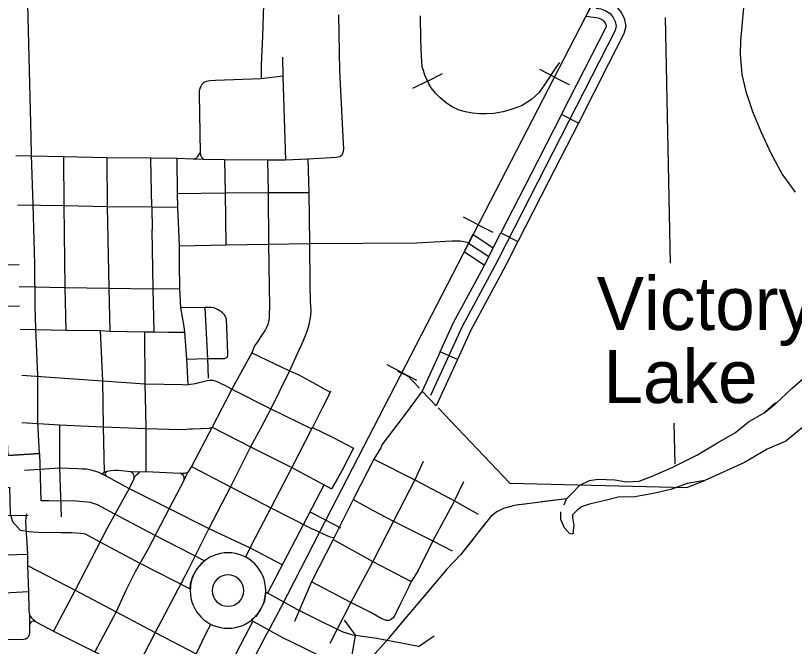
# Model space of a CAD drawing. Extents: x 1164457 to 1439835, y 1590918 to 1773502.
# Drawn here: x 1298324 to 1304504, y 1633633 to 1638642 of the extents above; entities that cross this region are included whole.
import ezdxf

# ---------------------------------------------------------------- set-up
doc = ezdxf.new("R2010")
doc.units = 0
for name, color, linetype in [('Level 15', 7, 'Continuous'), ('Level 24', 7, 'Continuous'), ('Level 31', 7, 'Continuous'), ('Level 33', 7, 'Continuous'), ('Level 34', 7, 'Continuous'), ('Level 35', 7, 'Continuous'), ('Level 37', 7, 'Continuous'), ('Level 40', 7, 'Continuous'), ('Level 43', 7, 'Continuous'), ('Level 5', 7, 'Continuous'), ('Level 6', 7, 'Continuous')]:
    doc.layers.add(name, color=color, linetype=linetype)

msp = doc.modelspace()

# ---------------------------------------------------------------- linework, layer by layer
at = {"layer": 'Level 15'}
for points in [[(1298513.3, 1635164.1), (1298499.6, 1635413.1), (1298499.8, 1635787.6), (1298484.8, 1636155.1), (1298480.5, 1636337.1), (1298476.5, 1636667.6), (1298463.9, 1637142.9), (1298451.5, 1637530.8), (1298447.9, 1637680.7), (1298415.1, 1638944.2), (1298391.3, 1639807.5), (1298141.4, 1639800.3)], [(1298141.4, 1639800.3), (1298165.2, 1638937.6), (1298197.9, 1637674.4), (1298201.6, 1637523.8), (1298214, 1637135.6), (1298226.5, 1636662.8), (1298230.6, 1636332.7), (1298234.9, 1636147.1), (1298249.8, 1635782.5), (1298249.6, 1635406.4), (1298263.8, 1635147.9), (1298513.3, 1635164.1)], [(1299709.5, 1634089.1), (1299713.1, 1634128.9), (1299731.6, 1634191.5), (1299764.3, 1634252.6), (1299823.2, 1634311.7), (1299430.5, 1634513.2), (1299110.4, 1634682.9), (1298975, 1634756), (1298917.6, 1634774.7), (1298863.9, 1634781.5), (1298775.7, 1634787.8), (1298686.6, 1634787.1), (1298587.9, 1634789.5), (1298548.2, 1634788.5), (1298528.1, 1634789.4), (1298516.2, 1635164.2), (1298056.3, 1635134.5), (1297302.4, 1635106.3), (1297059.9, 1635097.3), (1296805.9, 1635087.8), (1296448.4, 1635077.9), (1295766.2, 1635051.5), (1295337.8, 1635042.2)], [(1295337.8, 1635042.2), (1295343.3, 1634792.2), (1295773.7, 1634801.6), (1296456.7, 1634828), (1296814, 1634837.9), (1297069.3, 1634847.5), (1297311.7, 1634856.5), (1298069.1, 1634884.8), (1298274.5, 1634898.1), (1298281.3, 1634685.8), (1298300.3, 1634623.8), (1298360.7, 1634555.9), (1298432.6, 1634544.9), (1298463.5, 1634541.9), (1298546, 1634538.3), (1298588.1, 1634539.5), (1298684.6, 1634537.1), (1298767.8, 1634537.8), (1298839.2, 1634532.6), (1298862.6, 1634529.7), (1298876.1, 1634525.3), (1298992.5, 1634462.4), (1299314.9, 1634291.5), (1299709.5, 1634089.1)], [(1301022.5, 1633718.7), (1301000.5, 1633722.5), (1300977.5, 1633729.2), (1300924.1, 1633746.6), (1300872.6, 1633770.1), (1300722.2, 1633844.5), (1300558.7, 1633924.9), (1300308.9, 1634062.9), (1300305.7, 1634033.7), (1300298.5, 1633992.4), (1300268.7, 1633925.6), (1300230.3, 1633870.2), (1300194.6, 1633840.5)], [(1300194.6, 1633840.5), (1300443.1, 1633703.2), (1300611.5, 1633620.3), (1300765.2, 1633544.2), (1300833.2, 1633513.3), (1300904.1, 1633490.2), (1300944, 1633478.6), (1300979.3, 1633472.4), (1301022.5, 1633718.7)], [(1301522.1, 1633632.6), (1301191.7, 1633694.5), (1301022.5, 1633718.7)]]:
    msp.add_lwpolyline(points, dxfattribs=at)
at = {"layer": 'Level 24'}
for radius, start, end in [(300, 90, 270), (300, 270, 90), (125, 90, 270), (125, 270, 90)]:
    msp.add_arc((1300009.2, 1634076.3), radius, start, end, dxfattribs=at)
at = {"layer": 'Level 31'}
for p, q in [((1302789.7, 1637787.6), (1302656.1, 1637855.9)), ((1302175.4, 1636915.6), (1302308.9, 1636847.4)), ((1301830.1, 1635910.3), (1301693.7, 1635972.6))]:
    msp.add_line(p, q, dxfattribs=at)
for points in [[(1302848.5, 1638633.1), (1302922.4, 1638775.5), (1302987.8, 1638767.8), (1303043.1, 1638745.2), (1303092.8, 1638713.8), (1303128.4, 1638666.8), (1303152.1, 1638621.5), (1303167, 1638557), (1303151.7, 1638495.6), (1303030, 1638257.7)], [(1302930.9, 1638699), (1302968.9, 1638694.5), (1303008.7, 1638678.3), (1303041.2, 1638657.7), (1303064.9, 1638626.5), (1303081.2, 1638595.3), (1303089.9, 1638557.7), (1303081, 1638522.1), (1302154.7, 1636710.5), (1302103.5, 1636609.2), (1301867.2, 1636172.2), (1301617.5, 1635624.9)], [(1302896.5, 1638326), (1303010.3, 1638548.6), (1303012.8, 1638558.4), (1303010.3, 1638569), (1303001.4, 1638586.2), (1302989.7, 1638601.6), (1302974.2, 1638611.3), (1302950, 1638621.2), (1302848.5, 1638633.1)], [(1302656.1, 1637855.9), (1302896.5, 1638326)], [(1303030, 1638257.7), (1302789.7, 1637787.6)], [(1302656.1, 1637855.9), (1302415.7, 1637385.8)], [(1302789.7, 1637787.6), (1302549.3, 1637317.5)], [(1302415.7, 1637385.8), (1302175.4, 1636915.6)], [(1302549.3, 1637317.5), (1302308.9, 1636847.4)], [(1301953.4, 1636902.1), (1301884.1, 1636768), (1302045.6, 1636660)], [(1301931.7, 1636449.2), (1302037, 1636644), (1302087.9, 1636744.5), (1302175.4, 1636915.6)], [(1302045.6, 1636660), (1302113.7, 1636795), (1301953.4, 1636902.1)], [(1301918.7, 1636835), (1302079.4, 1636727.7)], [(1302308.9, 1636847.4), (1302221.6, 1636676.5), (1302169.9, 1636574.5), (1302063.6, 1636377.9)], [(1301693.7, 1635972.6), (1301800, 1636205.6), (1301931.7, 1636449.2)], [(1302063.6, 1636377.9), (1301934.3, 1636138.7), (1301830.1, 1635910.3)], [(1301693.7, 1635972.6), (1301551.1, 1635660)], [(1301830.1, 1635910.3), (1301662.4, 1635542.6), (1301551.1, 1635660)]]:
    msp.add_lwpolyline(points, dxfattribs=at)
at = {"layer": 'Level 33'}
for points in [[(1300290.7, 1638725.5), (1300282.5, 1638477.5), (1300273.1, 1638250), (1300273.9, 1638139.8)], [(1300887.2, 1638647.2), (1300895.4, 1638203.5), (1300918.2, 1637732.5), (1300923.9, 1637628.1), (1300926.3, 1637587.3), (1300923.9, 1637561.2), (1300915.7, 1637535.1), (1300909.2, 1637530.2), (1300897, 1637521.2), (1300882.5, 1637516.8), (1300867.6, 1637514.7), (1300824.4, 1637512.2), (1300644.2, 1637502.5), (1300465.2, 1637494.2), (1300324.2, 1637492.6), (1299982.8, 1637495.6), (1299819, 1637497.5), (1299734.2, 1637500.8), (1299603.8, 1637506.5), (1299397, 1637508.8), (1299049.1, 1637513.1), (1298704.4, 1637519.7), (1298326.6, 1637527.3)], [(1300442.3, 1638311.9), (1300445.6, 1638160.2), (1300465.2, 1637494.2)], [(1300445.6, 1638160.2), (1300273.9, 1638139.8), (1299909.5, 1638126.8), (1299867.9, 1638124.3), (1299836.9, 1638118.6), (1299816.5, 1638108.8), (1299801.8, 1638095), (1299793.7, 1638079.5), (1299787.2, 1638064), (1299781.5, 1638040.3), (1299781.5, 1638019.6), (1299789.7, 1637550.5)], [(1298704.4, 1637519.7), (1298708, 1637132.5), (1298715.4, 1636483.7), (1298722.8, 1636142.5)], [(1300644.2, 1637502.5), (1300651.9, 1637237.2), (1300656.9, 1636831.6), (1300659.3, 1636497.8), (1300662.3, 1636374.9), (1300666.1, 1636297.5), (1300665.4, 1636256.7), (1300649.9, 1636187.8), (1300650.4, 1636185.1), (1300637.5, 1636140.1), (1300615.3, 1636084.3), (1300595.8, 1636034.6), (1300572.9, 1635985.2), (1300498.3, 1635821.5), (1300348.1, 1635520.2), (1300268.2, 1635362.8), (1300188.1, 1635218.5), (1300029.6, 1634898.8), (1299858.6, 1634569.1), (1299690, 1634234.4), (1299432.1, 1633742.5), (1299268.3, 1633425.5)], [(1299404.1, 1637122), (1299401, 1637369), (1299397, 1637508.8)], [(1299603.8, 1637506.5), (1299606.3, 1637228), (1299607.9, 1637120.2), (1299621.5, 1636814.4), (1299622.7, 1636672.6), (1299624.3, 1636473.8), (1299631.8, 1636321.1), (1299660.3, 1636172.6), (1299663.6, 1636128.5), (1299680.9, 1635914.6), (1299691, 1635712.9)], [(1299734.2, 1637500.8), (1299756.3, 1637510.6), (1299770.9, 1637523.6), (1299789.7, 1637550.5), (1299791.3, 1637534.2), (1299800.3, 1637517.1), (1299819, 1637497.5)], [(1300324.2, 1637492.6), (1300327.4, 1637235.7), (1300331.1, 1636827.2), (1300337.6, 1636325), (1300337.2, 1636269.8), (1300335.7, 1636238.6), (1300330.9, 1636212.2), (1300325, 1636189.8), (1300311.4, 1636159.1), (1300303.2, 1636143.6), (1300264.9, 1636084.5), (1300242.5, 1636050.3), (1300221, 1636019.1), (1300198.7, 1635965), (1300039, 1635675.2), (1299884, 1635373.2), (1299718.8, 1635060.5), (1299691.4, 1635015.4), (1299667.2, 1634968), (1299658.7, 1634950.7), (1299543.2, 1634727.2), (1299372.7, 1634402.4), (1299273.8, 1634223.8), (1299196.9, 1634071.4), (1299121.5, 1633908.3), (1298952.3, 1633588.7)], [(1299982.8, 1637495.6), (1299987.9, 1637235.1), (1299992.3, 1636821.3)], [(1299606.3, 1637228), (1299987.9, 1637235.1)], [(1298338.9, 1637139.3), (1298708, 1637132.5), (1299051.9, 1637126.3), (1299404.1, 1637122), (1299607.9, 1637120.2)], [(1299051.9, 1637126.3), (1299063.9, 1636477.5), (1299072.2, 1636136.3)], [(1299424.7, 1636129.2), (1299415.6, 1636472.6), (1299408.5, 1636940.1)], [(1299621.5, 1636814.4), (1299992.3, 1636821.3), (1300331.1, 1636827.2), (1300656.9, 1636831.6), (1301505.6, 1636837.6), (1301786, 1636852.1), (1301851.1, 1636852.1), (1301868, 1636849.9), (1301921.2, 1636839.8)], [(1297988.3, 1636653.2), (1298351.5, 1636665.2)], [(1298352.2, 1636491.1), (1298715.4, 1636483.7), (1299063.9, 1636477.5), (1299415.6, 1636472.6), (1299624.3, 1636473.8)], [(1298355.5, 1636334.9), (1297988.5, 1636324.6), (1297695.9, 1636307.2), (1297369.9, 1636294.6), (1297084.8, 1636288.8), (1297071.6, 1636285.5), (1297057.4, 1636279), (1297047.3, 1636269.3), (1297042.8, 1636260.1), (1297039, 1636239.5), (1297039, 1636226), (1297039.9, 1636163.3), (1297055.2, 1635732.6), (1297058.4, 1635340.9), (1297064.6, 1634972.4)], [(1298359.8, 1636151.1), (1298722.8, 1636142.5), (1298994, 1636140), (1299072.2, 1636136.3), (1299346.8, 1636129.2), (1299424.7, 1636129.2), (1299536.2, 1636128.5), (1299663.6, 1636128.5)], [(1298994, 1636140), (1299012.8, 1635740.7), (1299018.3, 1635375.9), (1299026.4, 1635016.7)], [(1299346.8, 1636129.2), (1299349.8, 1635717.2), (1299354.1, 1635496.9), (1299358.4, 1635361.7), (1299358.6, 1635021.2)], [(1300198.7, 1635965), (1300498.3, 1635821.5), (1300523.3, 1635811.5), (1300571.9, 1635789.3), (1300659.2, 1635741.4), (1300820.8, 1635652.4)], [(1298374.8, 1635785.1), (1299012.8, 1635740.7), (1299349.8, 1635717.2), (1299649.7, 1635711), (1299668.8, 1635710), (1299691, 1635712.9), (1299711.7, 1635715.7), (1299751, 1635720), (1299781.8, 1635727.2), (1299832.7, 1635741.9), (1299846.3, 1635745.2), (1299859, 1635747.2), (1299885.5, 1635747.2), (1299906.2, 1635741.5), (1299928.1, 1635732.4), (1299958.7, 1635718.8), (1299983.9, 1635708.1), (1300039, 1635675.2), (1300348.1, 1635520.2), (1300673.9, 1635360.6)], [(1300823.8, 1635658.8), (1300796.9, 1635602.4), (1300756.9, 1635523.7), (1300682.3, 1635376.1), (1300676.9, 1635367), (1300518, 1635058.5), (1300352.3, 1634739.2), (1300261.8, 1634567.5), (1300188.9, 1634422.2), (1300147.5, 1634342.6)], [(1301551.1, 1635660), (1301398.7, 1635454.4), (1301229.9, 1635233.2), (1301221, 1635209.7), (1301166.2, 1635120.7), (1301001.5, 1634798.3), (1300851, 1634496.7), (1300843.2, 1634481), (1300671.1, 1634145.3), (1300536.1, 1633830.2)], [(1298374.6, 1635409.8), (1298672.4, 1635392.1), (1299018.3, 1635375.9), (1299358.4, 1635361.7), (1299633.7, 1635356.1), (1299679.7, 1635357.3), (1299705.8, 1635359), (1299728.8, 1635359.6), (1299861, 1635365.9), (1299884, 1635373.2)], [(1298672.4, 1635392.1), (1298671.7, 1635049.5), (1298685.6, 1634662.1)], [(1299884, 1635373.2), (1300188.1, 1635218.5), (1300515, 1635052.1), (1300830.1, 1634884.7)], [(1300679.2, 1635369.7), (1300843.7, 1635290.4), (1301005.5, 1635206.2)], [(1301166.2, 1635120.7), (1301492.3, 1634955.6)], [(1298395.3, 1635031.2), (1298671.7, 1635049.5), (1298818.2, 1635046.5), (1298851.3, 1635043.4), (1298888.1, 1635042.4), (1298911.3, 1635038), (1298951.3, 1635026.5), (1298981.8, 1635015.1), (1299007.4, 1635004.2), (1299044.6, 1634983.6), (1299225.2, 1634887.2), (1299543.2, 1634727.2), (1299858.6, 1634569.1), (1300185.8, 1634415.9), (1300440.7, 1634281.6)], [(1299007.4, 1635004.2), (1299026.4, 1635016.7), (1299037.7, 1635021.7), (1299049.7, 1635024.9), (1299080.5, 1635029.6), (1299111.2, 1635030.9), (1299139.2, 1635031.3), (1299239.3, 1635022.8), (1299310.8, 1635019), (1299358.6, 1635021.2), (1299629.8, 1635007.3), (1299663.3, 1635007.7), (1299676, 1635010), (1299691, 1635016.1)], [(1299718.8, 1635060.5), (1300029.6, 1634898.8), (1300349.3, 1634732.8), (1300666.3, 1634570.4), (1300816.7, 1634503.9), (1300851, 1634496.7)], [(1299044.6, 1634983.6), (1299037.3, 1634995.1), (1299036.5, 1634999.7), (1299037.3, 1635009.4), (1299040.4, 1635015.1), (1299049.7, 1635024.9)], [(1299239.3, 1635022.8), (1299247, 1635015.9), (1299254.7, 1635006.7), (1299259.3, 1634995.1), (1299263.1, 1634983.6), (1299261.7, 1634965.2), (1299271.6, 1634983.6), (1299285.4, 1634999), (1299300.8, 1635010.5), (1299310.8, 1635019)], [(1299629.8, 1635007.3), (1299640.2, 1635003.4), (1299648.3, 1634997.3), (1299657.1, 1634986.5), (1299658.7, 1634979.6), (1299659.8, 1634969.2), (1299658.7, 1634950.7)], [(1299261.7, 1634965.2), (1299261.4, 1634964), (1299225.2, 1634887.2), (1299051.4, 1634572.6), (1298796.1, 1634078.3), (1298625.8, 1633752.7)], [(1300773.3, 1634918.8), (1300609.5, 1634604.5), (1300322.5, 1634055.4)], [(1301492.3, 1634955.6), (1301322, 1634627.8), (1301159.1, 1634305.8), (1300984.1, 1633981.4), (1300818.9, 1633657.1)], [(1301807.4, 1634788.1), (1301635.1, 1634470.2), (1301518.5, 1634234.9), (1301484.4, 1634179.6), (1301464.2, 1634148.3), (1301444.9, 1634106.1), (1301382.1, 1633977.9), (1301331.6, 1633876.5), (1301319.9, 1633860.5), (1301299.9, 1633842.6), (1301284.5, 1633837.6), (1301265.9, 1633838.3), (1301247.3, 1633845.5), (1301225.8, 1633855.5), (1301147.1, 1633899.9), (1301085.6, 1633931.4), (1300984.1, 1633981.4), (1300671.1, 1634145.3)], [(1301001.5, 1634798.3), (1301157, 1634713.4), (1301322, 1634627.8), (1301635.1, 1634470.2)], [(1298424.1, 1634672.7), (1298072.2, 1634665.7), (1297326, 1634634.6), (1297095.6, 1634619.8), (1297080.8, 1634610.8), (1297072.2, 1634593.5), (1297072.2, 1634576.3), (1297086.5, 1634313.3), (1297099.7, 1634013.3)], [(1298411.8, 1634686.5), (1298405.8, 1634658.4), (1298402.2, 1634623), (1298417.7, 1634366.2), (1298418.6, 1634275), (1298425.9, 1634065.3), (1298429.6, 1633921.3), (1298434.7, 1633880.3), (1298450, 1633859.8), (1298475.6, 1633836.4), (1298490.3, 1633825.9), (1298625.8, 1633752.7), (1298952.3, 1633588.7), (1299268.3, 1633425.5), (1299586.9, 1633263.1), (1299848.7, 1633126.7)], [(1300842.6, 1634481.3), (1300843.2, 1634481), (1301159.1, 1634305.8), (1301464.2, 1634148.3)], [(1297086.5, 1634313.3), (1298082.9, 1634354.7), (1298417.7, 1634366.2)], [(1298418.6, 1634275), (1298796.1, 1634078.3), (1299121.5, 1633908.3), (1299432.1, 1633742.5), (1299757.4, 1633573.5), (1300002.9, 1633443.7)], [(1298425.9, 1634065.3), (1298092.8, 1634047.9), (1297110, 1634013.3), (1297099.7, 1634013.3), (1296779.7, 1633996), (1296266.3, 1633966.1), (1295806.8, 1633943.1)], [(1300206.7, 1633833.8), (1300004.5, 1633446.9), (1299850.5, 1633130.3), (1299684.8, 1632809.7), (1299519.5, 1632485.6), (1299360.3, 1632171), (1299355.2, 1632162.9), (1299195.3, 1631843.9), (1299023.6, 1631522.8), (1298863, 1631201.4), (1298719.7, 1630926.2), (1298554.7, 1630603.8)], [(1299872.6, 1633809.3), (1299829.6, 1633725.3), (1299760.4, 1633579.9), (1299589.9, 1633269.5), (1299420.6, 1632943.8), (1299254.9, 1632621.7), (1299093.2, 1632307.8), (1298930.2, 1631985.7), (1298823.1, 1631778.7), (1298764, 1631666.5), (1298605.4, 1631338)]]:
    msp.add_lwpolyline(points, dxfattribs=at)
at = {"layer": 'Level 34'}
for points in [[(1299049.1, 1637513.1), (1299051.9, 1637126.3)], [(1299987.9, 1637235.1), (1300327.4, 1637235.7), (1300651.9, 1637237.2)], [(1299404.1, 1637122), (1299408.5, 1636940.1)], [(1299680.9, 1635914.6), (1299846.4, 1635917.6), (1299983.6, 1635918.3), (1299990.6, 1635920.1), (1299996, 1635923.1), (1300001.2, 1635927.3), (1300004.9, 1635932.4), (1300007.8, 1635945.1), (1300008.6, 1635959.7), (1299997.7, 1636232.3), (1299990.7, 1636253.1), (1299982.1, 1636265.7), (1299966.4, 1636280), (1299955, 1636289.5), (1299932.2, 1636305.5), (1299915.8, 1636313.7), (1299897.5, 1636319.9), (1299872.3, 1636324.7), (1299851.9, 1636324.9), (1299829.2, 1636324.6), (1299825.1, 1636324.6), (1299631.8, 1636321.1)], [(1299825.1, 1636324.6), (1299846.4, 1635917.6), (1299852.6, 1635762.9)], [(1301005.5, 1635206.2), (1300916.3, 1635033.2), (1300876.6, 1634961.3), (1300830.1, 1634884.7)], [(1301556.9, 1635100.1), (1301492.3, 1634955.6)], [(1301492.3, 1634955.6), (1301807.4, 1634788.1), (1301994, 1634682.1)], [(1301807.4, 1634788.1), (1301881.2, 1634942.3)], [(1301635.1, 1634470.2), (1301787.7, 1634391)], [(1298434.7, 1633880.3), (1298434.7, 1633806.4), (1298434.7, 1633741.2), (1298429.5, 1633717.2), (1298423.2, 1633705.5), (1298415.6, 1633698.1), (1298401.8, 1633690), (1298386.4, 1633688.6), (1298104.7, 1633685.4)], [(1298490.3, 1633825.9), (1298472, 1633832.7), (1298463.2, 1633833.5), (1298452.8, 1633830), (1298447.6, 1633825.7), (1298441.3, 1633819.6), (1298434.7, 1633806.4)]]:
    msp.add_lwpolyline(points, dxfattribs=at)
at = {"layer": 'Level 35'}
for points in [[(1304276.9, 1639213.7), (1304219.2, 1639121.5), (1304189, 1639062.8), (1304163.9, 1639001.3), (1304146.5, 1638945.3), (1304098.9, 1638704.9), (1304076.3, 1638441.7), (1304072.3, 1638336.1), (1304088, 1638174.1), (1304118.4, 1638038), (1304171, 1637878.9), (1304238.5, 1637720.4), (1304315.7, 1637549.4), (1304408.9, 1637378.2), (1304510.5, 1637238.4)], [(1304263, 1635486.4), (1304354.2, 1635557.8), (1304482.3, 1635680.8), (1304677, 1635850)], [(1302677.1, 1634755.9), (1302695.7, 1634804.6), (1302741.2, 1634848.2), (1302800.1, 1634912.3), (1302877, 1634950.7), (1302943.6, 1634961), (1303079.4, 1634955.8), (1303169, 1634940.5), (1303271.5, 1634945.6), (1303374, 1634984), (1303532.8, 1635053.2), (1303730.1, 1635150.6), (1303894.1, 1635248), (1304037.5, 1635330), (1304140, 1635414.6), (1304263, 1635486.4), (1304352.7, 1635568.4)], [(1304568.8, 1635371.8), (1304436.2, 1635263.1), (1304288.9, 1635197.5), (1304109.3, 1635091.8), (1303792.5, 1634949.2), (1303652.7, 1634924.9), (1303524.6, 1634878.8), (1303383.7, 1634848), (1303237.7, 1634819.8), (1303104.5, 1634817.3), (1303012.2, 1634794.2), (1302877, 1634761.1), (1302815.5, 1634740.6), (1302774.5, 1634709.8), (1302743.7, 1634676.5), (1302743.7, 1634656), (1302754, 1634591.9), (1302748.9, 1634553.5), (1302748.9, 1634530.4), (1302738.6, 1634522.7), (1302718.1, 1634530.4), (1302679.7, 1634574), (1302651.5, 1634640.6), (1302651.5, 1634702.1)]]:
    msp.add_lwpolyline(points, dxfattribs=at)
at = {"layer": 'Level 37'}
for points in [[(1300932.4, 1633840.4), (1301020.5, 1633719)], [(1301522.1, 1633632.6), (1301645.9, 1633717.3)]]:
    msp.add_lwpolyline(points, dxfattribs=at)
at = {"layer": 'Level 40'}
for p, q in [((1302600.6, 1638153.7), (1302483.3, 1638214.4)), ((1301592.6, 1638121.6), (1301474.5, 1638062.6)), ((1301592.6, 1638121.6), (1301710.7, 1638180.6)), ((1302600.6, 1638153.7), (1302717.9, 1638093.1)), ((1301994.3, 1636981.2), (1301877.1, 1637041.8)), ((1301994.3, 1636981.2), (1302111.6, 1636920.6)), ((1301389.3, 1635808), (1301272, 1635868.5)), ((1301389.3, 1635808), (1301506.6, 1635747.6)), ((1300785.1, 1634634.4), (1300667.7, 1634694.8)), ((1300785.1, 1634634.4), (1300902.5, 1634574.1))]:
    msp.add_line(p, q, dxfattribs=at)
for points in [[(1304420.2, 1641670.9), (1304337.1, 1641509.4), (1304240.8, 1641324.4), (1303818.6, 1640506.1), (1303537.2, 1639967.8), (1303418.7, 1639735.3), (1303150.6, 1639212.9), (1302886.6, 1638706.9), (1301917.5, 1636832.7), (1301040.4, 1635131.3), (1300738.6, 1634543.8), (1300431.2, 1633946.9), (1300340.4, 1633776.4)], [(1304240.8, 1641324.4), (1303818.6, 1640506.1), (1303537.2, 1639967.8), (1303418.7, 1639735.3), (1303150.6, 1639212.9), (1302886.6, 1638706.9), (1301917.5, 1636832.7), (1301040.4, 1635131.3), (1300738.6, 1634543.8), (1300431.2, 1633946.9), (1300340.4, 1633776.4), (1300318, 1633735.2), (1300191.2, 1633490.9)], [(1302641.3, 1638268.4), (1302625.5, 1638249.8), (1302616.6, 1638237.6), (1302539.5, 1638120.4), (1302479.4, 1638031.6), (1302417.9, 1637974.4), (1302345, 1637928.6), (1302264.8, 1637898.6), (1302193.3, 1637877.1), (1302118.9, 1637864.2), (1302058.9, 1637861.3), (1302005.9, 1637861.3), (1301950.1, 1637865.6), (1301894.3, 1637877.1), (1301844.3, 1637891.4), (1301787.1, 1637915.7), (1301742.7, 1637945.8), (1301692.6, 1637988.7), (1301656.9, 1638024.5), (1301622.5, 1638068.8), (1301603.9, 1638098.9), (1301589.6, 1638127.5), (1301572.5, 1638167.6), (1301559.6, 1638206.2), (1301551, 1638232), (1301546.7, 1638276.3), (1301543.9, 1638316.4), (1301539.6, 1638448.1), (1301538.1, 1638638.4)], [(1302641.3, 1638268.4), (1302625.5, 1638249.8), (1302616.6, 1638237.6), (1302539.5, 1638120.4), (1302479.4, 1638031.6), (1302417.9, 1637974.4), (1302345, 1637928.6), (1302264.8, 1637898.6), (1302193.3, 1637877.1), (1302118.9, 1637864.2), (1302058.9, 1637861.3), (1302005.9, 1637861.3), (1301950.1, 1637865.6), (1301894.3, 1637877.1), (1301844.3, 1637891.4), (1301787.1, 1637915.7), (1301742.7, 1637945.8), (1301692.6, 1637988.7), (1301656.9, 1638024.5), (1301622.5, 1638068.8), (1301603.9, 1638098.9), (1301589.6, 1638127.5), (1301572.5, 1638167.6), (1301559.6, 1638206.2), (1301551, 1638232), (1301546.7, 1638276.3), (1301543.9, 1638316.4), (1301539.6, 1638448.1), (1301538.1, 1638638.4)], [(1300340.4, 1633776.4), (1300318, 1633735.2), (1300191.2, 1633490.9), (1300062, 1633236.7), (1299881.1, 1632885.9), (1299702.3, 1632539.5), (1299475.9, 1632101.8), (1299180.5, 1631526.5), (1298885.7, 1630957.4)]]:
    msp.add_lwpolyline(points, dxfattribs=at)
at = {"layer": 'Level 43'}
for points in [[(1302695.7, 1634804.6), (1302384.4, 1634764.9), (1302296, 1634754.6), (1302242.6, 1634742), (1302215, 1634732.7), (1302194.8, 1634726.5), (1302141.7, 1634701.5), (1302097.4, 1634666.4), (1302050.9, 1634608.5), (1301853.5, 1634360), (1301746.2, 1634245.5), (1301302.1, 1633719.5), (1301286.6, 1633699.1), (1300983.1, 1633359.6), (1300983.4, 1633356.7), (1300970.2, 1633339), (1300950.6, 1633316.9), (1300897.8, 1633238), (1300846.2, 1633189.1), (1300808.4, 1633161.2), (1300769.3, 1633123.4), (1300752.5, 1633099.7), (1300737.2, 1633048), (1300543.7, 1632405.1)], [(1302695.7, 1634804.6), (1302499.3, 1634779.6)], [(1302368.3, 1634763), (1302296, 1634754.6), (1302242.6, 1634742), (1302215, 1634732.7), (1302194.8, 1634726.5), (1302141.7, 1634701.5), (1302097.4, 1634666.4), (1302050.9, 1634608.5), (1302033.1, 1634586.1)], [(1301951, 1634482.8), (1301853.5, 1634360), (1301746.2, 1634245.5), (1301693.1, 1634182.6)], [(1301607.9, 1634081.8), (1301352.5, 1633779.2)]]:
    msp.add_lwpolyline(points, dxfattribs=at)
at = {"layer": 'Level 5'}
for points in [[(1303477.3, 1638627), (1303519.4, 1636675.5)], [(1303546.9, 1635405.7), (1303553.9, 1635079.8)]]:
    msp.add_lwpolyline(points, dxfattribs=at)
at = {"layer": 'Level 6'}
for points in [[(1301353.6, 1635818.8), (1301418.8, 1635787.7), (1301441.5, 1635774.7), (1301474.1, 1635741.1), (1301528.7, 1635683.5)], [(1301676.3, 1635527.9), (1302245.2, 1634928.3), (1303650.5, 1634893.5)], [(1303650.5, 1634893.5), (1303792.5, 1634949.2)]]:
    msp.add_lwpolyline(points, dxfattribs=at)

# ---------------------------------------------------------------- texts
at = {"layer": 'Level 35'}
for s, p in [('Victory', (1302934.7, 1636145)), ('Lake', (1302988.5, 1635564.7))]:
    msp.add_text(s, height=422, dxfattribs=at).set_placement(p)

doc.saveas('drawing.dxf')
